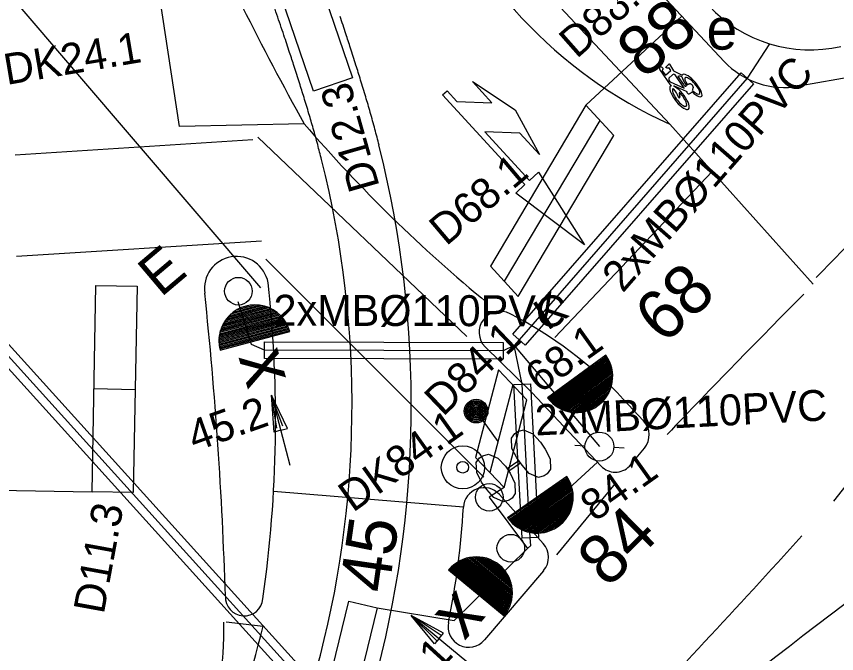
# Model space of a CAD drawing. Extents: x 81617 to 82144, y 454649 to 455150.
# Drawn here: x 81851.04 to 81870.9, y 454865.61 to 454881.04 of the extents above; entities that cross this region are included whole.
import ezdxf

# ---------------------------------------------------------------- set-up
doc = ezdxf.new("R2010")
doc.units = 0
for name, color, linetype in [('B-WE-OG-TOPOGRAFIE-G', 7, 'Continuous'), ('B-WE-VW-MARKERING-G', 7, 'Continuous'), ('N-OI-KL-VRI_KABEL_DETECTIE-G', 7, 'Continuous'), ('N-OI-KL-VRI_KABELGEUL-G', 7, 'Continuous'), ('N-OI-KL-VRI_LUS_DETECTIE-G', 7, 'Continuous'), ('N-OI-KL-VRI_LUS_DETECTIE-T18', 7, 'Continuous'), ('N-OI-KL-VRI_MANTELBUIS-G', 7, 'Continuous'), ('N-OI-KL-VRI_MANTELBUIS-T18', 7, 'Continuous'), ('N-WE-VW-VRI_ARMATUUR-S', 7, 'Continuous'), ('N-WE-VW-VRI_ARMATUUR-T18', 7, 'Continuous'), ('N-WE-VW-VRI_MAST-S', 7, 'Continuous'), ('N-WE-VW-VRI_RICHTINGNUMMER-T25', 7, 'Continuous')]:
    doc.layers.add(name, color=color, linetype=linetype)

msp = doc.modelspace()

# ---------------------------------------------------------------- linework, layer by layer
at = {"layer": 'B-WE-OG-TOPOGRAFIE-G'}
for p, q in [((81874.916, 454880.226), (81869.99, 454879.351)), ((81865.887, 454870.153), (81866.25, 454870.587))]:
    msp.add_line(p, q, dxfattribs=at)
for points in [[(81860.972, 454887.667), (81868.18, 454879.955)], [(81865.202, 454870.155), (81863.528, 454871.935), (81862.392, 454873.039)], [(81866.231, 454871.25), (81865.736, 454871.776)], [(81862.738, 454869.464), (81863.801, 454868.278)], [(81863.809, 454867.62), (81862.375, 454865.942)]]:
    msp.add_lwpolyline(points, dxfattribs=at)
for centre, radius, start, end in [((81384.425, 454720.912), 499.315, 18.68062, 18.74174), ((81759.42, 454847.652), 104.917, 18.31393, 18.55839), ((81739.67, 454841.022), 124.315, 18.55839, 18.68062), ((81759.42, 454847.652), 103.482, 18.31393, 18.55839), ((81795.02, 454859.436), 67.417, 18.00835, 18.31393), ((81795.02, 454859.436), 65.982, 18.00835, 18.31393), ((81804.078, 454862.38), 57.893, 17.58054, 18.00835), ((81869.641, 454881.321), 2, 223.0627, 280.0658), ((81804.078, 454862.38), 56.458, 17.5805, 18.0084), ((81816.845, 454866.425), 44.5, 17.0916, 17.5805), ((81816.845, 454866.425), 43.065, 17.0916, 17.5805), ((81821.112, 454867.737), 40.036, 16.4805, 17.0916), ((81821.112, 454867.737), 38.601, 16.4805, 17.0916), ((81827.65, 454869.672), 33.218, 15.8082, 16.4805), ((81827.65, 454869.672), 31.783, 15.8082, 16.4805), ((81830.107, 454870.367), 30.665, 15.0137, 15.8082), ((81830.107, 454870.367), 29.23, 15.0137, 15.8082), ((81834.087, 454871.435), 26.544, 14.1581, 15.0137), ((81834.856, 454871.629), 25.75, 315.1816, 14.1581), ((81834.087, 454871.435), 25.109, 14.1581, 15.0137), ((81834.856, 454871.629), 24.315, 315.1816, 14.1581), ((81856.374, 454874.452), 0.778, 10.5418, 188.3506), ((81826.72, 454871.27), 30.6, 351.8658, 6.2376), ((81757.01, 454863.938), 99.142, 1.77049, 6.02243), ((81862.757, 454873.393), 0.509, 61.9136, 224.1208), ((81858.393, 454864.888), 10.069, 43.1684, 62.7893), ((81865.867, 454870.908), 0.5, 320.0619, 43.2284), ((81865.545, 454870.475), 0.47, 222.9388, 316.7315), ((81862.366, 454869.13), 0.5, 41.8831, 176.883), ((81842.97, 454870.186), 18.925, 348.3581, 356.883), ((81863.429, 454867.945), 0.5, 319.4909, 41.8831), ((81856.559, 454866.98), 0.455, 177.4091, 354.9634), ((81861.995, 454866.266), 0.5, 168.3581, 319.4909)]:
    msp.add_arc(centre, radius, start, end, dxfattribs=at)
at = {"layer": 'B-WE-VW-MARKERING-G'}
for p, q in [((81854.993, 454878.378), (81853.979, 454885.079)), ((81856.964, 454874.469), (81850.333, 454882.22)), ((81862.559, 454878.95), (81862.086, 454879.466)), ((81862.086, 454879.466), (81863.118, 454878.784)), ((81861.364, 454879.143), (81861.475, 454879.244)), ((81863.359, 454876.969), (81861.364, 454879.143)), ((81861.475, 454879.244), (81861.712, 454878.986)), ((81861.712, 454878.986), (81862.559, 454878.95)), ((81863.118, 454878.784), (81863.709, 454877.697)), ((81866.865, 454878.432), (81870.34, 454874.562)), ((81863.235, 454878.213), (81862.388, 454878.25)), ((81862.388, 454878.25), (81863.469, 454877.071)), ((81863.709, 454877.697), (81863.235, 454878.213)), ((81851.016, 454877.689), (81856.772, 454878.062)), ((81856.894, 454878.118), (81861.952, 454873.29)), ((81863.469, 454877.071), (81863.69, 454877.273)), ((81863.69, 454877.273), (81864.8, 454875.509)), ((81867.894, 454877.286), (81864.079, 454873.271)), ((81863.138, 454876.766), (81863.359, 454876.969)), ((81864.8, 454875.509), (81863.138, 454876.766)), ((81851.048, 454875.238), (81856.977, 454875.611)), ((81857.08, 454875.163), (81862.361, 454869.888)), ((81857.003, 454874.502), (81857.002, 454874.502)), ((81865.114, 454870.249), (81863.429, 454868.694)), ((81865.539, 454869.733), (81864.122, 454868.002)), ((81861.867, 454869.157), (81857.268, 454869.534)), ((81856.127, 454866.379), (81857.019, 454866.277))]:
    msp.add_line(p, q, dxfattribs=at)
for points in [[(81860.959, 454884.75), (81866.865, 454878.432)], [(81866.902, 454879.365), (81866.629, 454879.747)], [(81866.661, 454879.824), (81866.706, 454879.784)], [(81866.681, 454879.727), (81866.76, 454879.618), (81866.89, 454879.737), (81866.842, 454879.807)], [(81866.862, 454879.889), (81866.957, 454879.73)], [(81866.931, 454879.63), (81866.844, 454879.551)], [(81866.878, 454879.457), (81867.215, 454879.31), (81866.998, 454879.63)], [(81866.957, 454879.73), (81867.167, 454879.625)], [(81867.061, 454879.585), (81867.194, 454879.392)], [(81866.975, 454879.361), (81867.263, 454879.234)], [(81867.417, 454879.247), (81867.417, 454879.247)], [(81858.01, 454878.446), (81854.993, 454878.378)]]:
    msp.add_lwpolyline(points, dxfattribs=at)
for centre, radius, start, end in [((81871.56, 454888.74), 11.327, 200.6243, 245.5093), ((81921.727, 454913.877), 72.905, 206.56935, 209.07707), ((82219.514, 454535.314), 486.895, 134.97926, 135.80708), ((81885.224, 454901.84), 35.888, 220.6875, 230.6195), ((81983.253, 454780.99), 142.962, 137.48788, 141.84973), ((82014.316, 454730.536), 203.636, 135.08452, 136.41908), ((81999.362, 454697.85), 212.13, 125.19968, 128.77534), ((81664.878, 455054.559), 277.009, 316.35043, 317.79319), ((81845.809, 454866.259), 10.261, 343.8323, 0.6213), ((81823.555, 454874.579), 34.479, 339.7444, 346.0669)]:
    msp.add_arc(centre, radius, start, end, dxfattribs=at)
for centre, major_axis, ratio, start_param, end_param in [((81866.74, 454879.732), (-0.0412, 0.0452), 0.951466, 6.106821, 7.217969), ((81866.911, 454879.52), (-0.0503, 0.0552), 0.951466, 0.416101, 1.916869), ((81866.966, 454879.588), (-0.0374, 0.0411), 0.951466, 4.868752, 6.235806), ((81867.403, 454879.371), (0.229, -0.262), 0.311979, 3.55346, 4.48315), ((81867.403, 454879.371), (0.229, -0.262), 0.311979, 5.055467, 9.526588), ((81867.411, 454879.363), (0.175, -0.195), 0.298624, 5.035956, 10.606751), ((81867.1, 454879.078), (0.217, -0.277), 0.337195, 2.965544, 8.864445), ((81867.403, 454879.371), (0.229, -0.262), 0.311979, 4.48315, 4.485286), ((81867.411, 454879.363), (0.175, -0.195), 0.298624, 4.323566, 4.330384), ((81867.101, 454879.079), (-0.163, 0.211), 0.305781, 6.11811, 11.365094), ((81866.943, 454879.273), (-0.0162, 0.0177), 0.951466, 4.515962, 5.19261), ((81866.627, 454878.971), (-0.325, 0.357), 0.951466, 4.25523, 4.724374), ((81867.349, 454879.175), (-0.177, 0.194), 0.951466, 0.769914, 1.166655), ((81867.099, 454879.198), (-0.00368, 0.00403), 0.951466, 5.132399, 7.244068), ((81867.093, 454879.093), (-0.0124, 0.0136), 0.951466, 0.933004, 4.202582)]:
    msp.add_ellipse(centre, major_axis=major_axis, ratio=ratio, start_param=start_param, end_param=end_param, dxfattribs=at)
for points in [[(81866.629, 454879.747), (81866.621, 454879.772), (81866.622, 454879.789), (81866.632, 454879.813), (81866.654, 454879.827), (81866.661, 454879.824)], [(81866.773, 454879.81), (81866.771, 454879.813), (81866.772, 454879.816), (81866.773, 454879.818), (81866.775, 454879.821), (81866.786, 454879.831), (81866.807, 454879.853), (81866.822, 454879.869), (81866.835, 454879.88), (81866.841, 454879.885), (81866.846, 454879.892), (81866.851, 454879.896), (81866.853, 454879.896), (81866.855, 454879.897), (81866.856, 454879.896), (81866.858, 454879.894), (81866.86, 454879.891), (81866.862, 454879.889), (81866.863, 454879.886)], [(81866.842, 454879.807), (81866.832, 454879.798), (81866.816, 454879.792), (81866.799, 454879.794), (81866.784, 454879.801), (81866.773, 454879.81)], [(81867.161, 454879.582), (81867.113, 454879.593), (81867.087, 454879.593), (81867.061, 454879.585)], [(81866.965, 454879.353), (81866.962, 454879.359), (81866.964, 454879.363), (81866.975, 454879.361)], [(81867.194, 454879.392), (81867.211, 454879.373), (81867.225, 454879.363), (81867.241, 454879.357), (81867.272, 454879.361)], [(81867.291, 454879.387), (81867.304, 454879.397), (81867.316, 454879.405), (81867.335, 454879.413), (81867.345, 454879.416), (81867.353, 454879.416), (81867.364, 454879.414), (81867.38, 454879.405), (81867.409, 454879.375), (81867.417, 454879.361), (81867.427, 454879.34), (81867.429, 454879.324), (81867.426, 454879.31), (81867.417, 454879.284), (81867.41, 454879.252)], [(81867.263, 454879.234), (81867.268, 454879.23), (81867.273, 454879.224), (81867.278, 454879.216), (81867.279, 454879.208), (81867.284, 454879.196), (81867.291, 454879.186), (81867.3, 454879.178), (81867.311, 454879.17), (81867.325, 454879.167), (81867.335, 454879.168), (81867.361, 454879.182), (81867.375, 454879.192), (81867.404, 454879.214)]]:
    msp.add_spline(points, degree=3, dxfattribs=at)
at = {"layer": 'N-OI-KL-VRI_KABEL_DETECTIE-G'}
for p, q in [((81864.836, 454878.895), (81867.16, 454881.046)), ((81847.104, 454869.626), (81852.875, 454869.531)), ((81862.852, 454869.634), (81862.493, 454869.399)), ((81859.776, 454866.72), (81861.647, 454866.417))]:
    msp.add_line(p, q, dxfattribs=at)
at = {"layer": 'N-OI-KL-VRI_KABELGEUL-G'}
for p, q in [((81863.097, 454873.073), (81865.161, 454870.624)), ((81862.493, 454869.399), (81863.421, 454868.157))]:
    msp.add_line(p, q, dxfattribs=at)
for points in [[(81869.281, 454880.381), (81868.742, 454879.546), (81863.215, 454873.214), (81863.097, 454873.073), (81862.831, 454872.946), (81857.049, 454872.96), (81856.734, 454873.094), (81856.416, 454874.128)], [(81862.44, 454851.616), (81862.582, 454852.027), (81862.754, 454852.346), (81865.008, 454854.754), (81865.955, 454855.815), (81865.903, 454856.153), (81846.599, 454877.513), (81846.252, 454877.634), (81845.96, 454877.281), (81846.114, 454876.473)], [(81861.647, 454866.417), (81863.421, 454868.157), (81863.498, 454868.233), (81863.487, 454868.417), (81863.292, 454872.136), (81863.097, 454873.073)]]:
    msp.add_lwpolyline(points, dxfattribs=at)
msp.add_arc((81870.263, 454883.584), 3.35, 223.0627, 282.8439, dxfattribs=at)
at = {"layer": 'N-OI-KL-VRI_LUS_DETECTIE-G'}
for p, q in [((81864.836, 454878.895), (81862.52, 454874.998)), ((81865.511, 454878.156), (81864.836, 454878.895)), ((81865.173, 454878.525), (81862.857, 454874.629)), ((81863.195, 454874.26), (81865.511, 454878.156)), ((81862.52, 454874.998), (81863.195, 454874.26)), ((81862.716, 454872.481), (81862.161, 454870.359)), ((81863.406, 454871.754), (81862.716, 454872.481)), ((81852.923, 454872.03), (81853.922, 454872.011)), ((81863.061, 454872.117), (81862.506, 454869.997)), ((81862.852, 454869.634), (81863.406, 454871.754)), ((81862.161, 454870.359), (81862.852, 454869.634))]:
    msp.add_line(p, q, dxfattribs=at)
for points in [[(81859.18, 454879.556), (81858.234, 454879.234), (81855.008, 454888.699), (81855.953, 454889.021)], [(81853.874, 454869.511), (81852.875, 454869.531), (81852.971, 454874.529), (81853.971, 454874.511)], [(81859.066, 454863.805), (81858.387, 454863.97), (81859.095, 454866.885), (81859.776, 454866.72)]]:
    msp.add_lwpolyline(points, close=True, dxfattribs=at)
at = {"layer": 'N-OI-KL-VRI_MANTELBUIS-G'}
for points in [[(81868.591, 454879.677), (81868.892, 454879.414), (81863.365, 454873.082), (81863.064, 454873.346)], [(81866.052, 454856.287), (81865.755, 454856.019), (81846.451, 454877.379), (81846.747, 454877.647)], [(81862.831, 454873.146), (81862.83, 454872.746), (81857.048, 454872.76), (81857.049, 454873.16)], [(81863.092, 454872.126), (81863.491, 454872.147), (81863.686, 454868.427), (81863.287, 454868.406)]]:
    msp.add_lwpolyline(points, close=True, dxfattribs=at)
at = {"layer": 'N-WE-VW-VRI_ARMATUUR-S'}
for p, q in [((81856.125, 454873.715), (81857.158, 454873.991)), ((81856.159, 454873.754), (81857.112, 454874.008)), ((81856.195, 454873.796), (81857.058, 454874.026)), ((81856.24, 454873.838), (81856.998, 454874.041)), ((81856.298, 454873.884), (81856.924, 454874.052)), ((81856.375, 454873.936), (81856.832, 454874.059)), ((81856.534, 454874.01), (81856.659, 454874.044)), ((81855.972, 454873.394), (81857.451, 454873.788)), ((81855.982, 454873.427), (81857.428, 454873.813)), ((81855.991, 454873.461), (81857.403, 454873.838)), ((81856.005, 454873.496), (81857.375, 454873.861)), ((81856.017, 454873.531), (81857.344, 454873.884)), ((81856.033, 454873.565), (81857.313, 454873.907)), ((81856.053, 454873.602), (81857.279, 454873.929)), ((81856.075, 454873.639), (81857.242, 454873.951)), ((81856.099, 454873.676), (81857.201, 454873.97)), ((81855.947, 454873.202), (81857.57, 454873.635)), ((81855.948, 454873.232), (81857.553, 454873.661)), ((81855.948, 454873.17), (81857.584, 454873.607)), ((81855.948, 454873.139), (81857.599, 454873.58)), ((81855.949, 454873.264), (81857.536, 454873.69)), ((81855.953, 454873.296), (81857.517, 454873.713)), ((81855.96, 454873.328), (81857.496, 454873.736)), ((81855.966, 454873.359), (81857.476, 454873.764)), ((81855.95, 454873.109), (81857.614, 454873.552)), ((81855.955, 454873.079), (81857.624, 454873.525)), ((81855.959, 454873.049), (81857.635, 454873.497)), ((81855.963, 454873.019), (81857.647, 454873.469)), ((81855.971, 454872.99), (81857.655, 454873.439)), ((81855.976, 454872.96), (81857.666, 454873.411)), ((81865.316, 454872.837), (81863.904, 454871.806)), ((81865.332, 454872.811), (81863.923, 454871.783)), ((81865.35, 454872.787), (81863.943, 454871.758)), ((81865.364, 454872.761), (81863.963, 454871.735)), ((81865.379, 454872.735), (81863.983, 454871.713)), ((81865.394, 454872.706), (81864.004, 454871.693)), ((81865.406, 454872.68), (81864.027, 454871.671)), ((81865.419, 454872.652), (81864.051, 454871.651)), ((81865.43, 454872.621), (81864.074, 454871.633)), ((81865.439, 454872.593), (81864.1, 454871.613)), ((81865.451, 454872.562), (81864.126, 454871.594)), ((81865.458, 454872.532), (81864.152, 454871.579)), ((81865.465, 454872.5), (81864.179, 454871.562)), ((81865.47, 454872.468), (81864.209, 454871.546)), ((81865.476, 454872.434), (81864.24, 454871.532)), ((81865.48, 454872.4), (81864.27, 454871.516)), ((81865.483, 454872.364), (81864.303, 454871.503)), ((81865.483, 454872.328), (81864.338, 454871.492)), ((81865.482, 454872.29), (81864.374, 454871.481)), ((81865.481, 454872.251), (81864.412, 454871.471)), ((81865.477, 454872.211), (81864.452, 454871.463)), ((81865.469, 454872.169), (81864.494, 454871.454)), ((81865.461, 454872.126), (81864.538, 454871.452)), ((81865.45, 454872.078), (81864.587, 454871.448)), ((81865.433, 454872.031), (81864.635, 454871.449)), ((81857.217, 454871.869), (81857.668, 454870.179)), ((81857.605, 454871.066), (81857.217, 454871.869)), ((81857.282, 454870.978), (81857.217, 454871.869)), ((81865.414, 454871.977), (81864.693, 454871.451)), ((81865.386, 454871.923), (81864.755, 454871.459)), ((81865.351, 454871.86), (81864.828, 454871.475)), ((81857.349, 454871.072), (81857.242, 454871.708)), ((81857.493, 454871.117), (81857.271, 454871.716)), ((81865.296, 454871.782), (81864.916, 454871.502)), ((81865.175, 454871.657), (81865.072, 454871.579)), ((81862.344, 454871.243), (81862.698, 454870.746)), ((81857.443, 454871.023), (81857.282, 454870.978)), ((81857.443, 454871.023), (81857.605, 454871.066)), ((81863.187, 454870.993), (81863.323, 454871.028)), ((81863.323, 454871.028), (81863.549, 454870.933)), ((81863.031, 454870.827), (81863.113, 454870.942)), ((81863.044, 454870.581), (81863.031, 454870.827)), ((81863.113, 454870.942), (81863.187, 454870.993)), ((81863.549, 454870.933), (81863.736, 454870.736)), ((81863.736, 454870.736), (81863.851, 454870.566)), ((81862.26, 454870.351), (81862.338, 454870.403)), ((81862.338, 454870.403), (81862.473, 454870.438)), ((81862.473, 454870.438), (81862.698, 454870.346)), ((81863.165, 454870.354), (81863.044, 454870.581)), ((81863.851, 454870.566), (81863.967, 454870.325)), ((81862.18, 454870.239), (81862.26, 454870.351)), ((81862.192, 454869.996), (81862.18, 454870.239)), ((81862.698, 454870.346), (81862.884, 454870.151)), ((81863.213, 454870.279), (81862.929, 454870.083)), ((81863.247, 454870.225), (81862.964, 454870.027)), ((81863.287, 454870.174), (81863.165, 454870.354)), ((81863.967, 454870.325), (81863.977, 454870.081)), ((81862.884, 454870.151), (81862.999, 454869.981)), ((81863.461, 454869.975), (81863.287, 454870.174)), ((81863.977, 454870.081), (81863.898, 454869.964)), ((81862.309, 454869.767), (81862.192, 454869.996)), ((81864.371, 454869.897), (81862.935, 454868.903)), ((81864.388, 454869.872), (81862.952, 454868.88)), ((81864.405, 454869.847), (81862.972, 454868.855)), ((81864.418, 454869.82), (81862.991, 454868.832)), ((81862.999, 454869.981), (81863.114, 454869.736)), ((81863.687, 454869.878), (81863.461, 454869.975)), ((81863.822, 454869.915), (81863.687, 454869.878)), ((81863.898, 454869.964), (81863.822, 454869.915)), ((81862.433, 454869.587), (81862.309, 454869.767)), ((81864.434, 454869.794), (81863.011, 454868.809)), ((81864.447, 454869.765), (81863.033, 454868.788)), ((81864.459, 454869.736), (81863.053, 454868.765)), ((81864.472, 454869.709), (81863.077, 454868.746)), ((81864.481, 454869.679), (81863.101, 454868.726)), ((81863.114, 454869.736), (81863.124, 454869.489)), ((81864.49, 454869.651), (81863.124, 454868.705)), ((81864.501, 454869.618), (81863.151, 454868.686)), ((81862.606, 454869.389), (81862.433, 454869.587)), ((81863.124, 454869.489), (81863.048, 454869.374)), ((81864.506, 454869.589), (81863.177, 454868.671)), ((81864.513, 454869.558), (81863.202, 454868.653)), ((81864.516, 454869.523), (81863.234, 454868.635)), ((81864.523, 454869.491), (81863.264, 454868.622)), ((81864.526, 454869.457), (81863.292, 454868.604)), ((81864.527, 454869.419), (81863.326, 454868.592)), ((81862.836, 454869.29), (81862.606, 454869.389)), ((81862.972, 454869.326), (81862.836, 454869.29)), ((81863.048, 454869.374), (81862.972, 454869.326)), ((81864.528, 454869.383), (81863.36, 454868.579)), ((81864.526, 454869.345), (81863.395, 454868.566)), ((81864.524, 454869.307), (81863.434, 454868.557)), ((81864.518, 454869.267), (81863.474, 454868.546)), ((81864.507, 454869.225), (81863.514, 454868.536)), ((81864.501, 454869.182), (81863.56, 454868.532)), ((81864.486, 454869.135), (81863.609, 454868.529)), ((81864.47, 454869.09), (81863.655, 454868.527)), ((81864.447, 454869.036), (81863.715, 454868.528)), ((81864.421, 454868.981), (81863.777, 454868.536)), ((81864.383, 454868.918), (81863.848, 454868.549)), ((81864.327, 454868.843), (81863.937, 454868.573)), ((81864.199, 454868.721), (81864.094, 454868.646)), ((81861.739, 454867.837), (81863.008, 454866.794)), ((81861.769, 454867.852), (81863.015, 454866.823)), ((81861.798, 454867.865), (81863.025, 454866.854)), ((81861.827, 454867.88), (81863.034, 454866.887)), ((81861.86, 454867.893), (81863.039, 454866.921)), ((81861.89, 454867.906), (81863.046, 454866.954)), ((81861.925, 454867.916), (81863.052, 454866.989)), ((81861.961, 454867.926), (81863.054, 454867.026)), ((81861.996, 454867.936), (81863.055, 454867.063)), ((81862.035, 454867.943), (81863.055, 454867.101)), ((81862.073, 454867.949), (81863.053, 454867.143)), ((81862.118, 454867.952), (81863.053, 454867.185)), ((81862.161, 454867.956), (81863.044, 454867.229)), ((81862.211, 454867.956), (81863.033, 454867.277)), ((81862.259, 454867.952), (81863.021, 454867.324)), ((81862.316, 454867.947), (81863.005, 454867.377)), ((81862.377, 454867.934), (81862.981, 454867.438)), ((81862.446, 454867.916), (81862.948, 454867.505)), ((81862.535, 454867.881), (81862.901, 454867.582)), ((81861.507, 454867.638), (81862.857, 454866.528)), ((81861.529, 454867.659), (81862.876, 454866.551)), ((81861.547, 454867.683), (81862.895, 454866.577)), ((81861.571, 454867.703), (81862.91, 454866.601)), ((81861.592, 454867.724), (81862.927, 454866.625)), ((81861.615, 454867.747), (81862.943, 454866.651)), ((81861.638, 454867.765), (81862.957, 454866.681)), ((81861.661, 454867.785), (81862.97, 454866.706)), ((81861.687, 454867.802), (81862.983, 454866.735)), ((81861.714, 454867.819), (81862.995, 454866.764)), ((81862.686, 454867.795), (81862.789, 454867.714)), ((81860.603, 454866.537), (81861.949, 454865.424)), ((81861.169, 454865.85), (81860.603, 454866.537)), ((81861.382, 454866.109), (81860.603, 454866.537)), ((81861.333, 454866.048), (81860.603, 454866.537)), ((81861.226, 454865.917), (81860.603, 454866.537)), ((81861.277, 454865.978), (81861.382, 454866.109)), ((81861.277, 454865.978), (81861.169, 454865.85))]:
    msp.add_line(p, q, dxfattribs=at)
for centre, radius in [((81862.175, 454871.484), 0.286), ((81862.175, 454871.484), 0.256), ((81862.175, 454871.484), 0.226), ((81862.175, 454871.484), 0.196), ((81862.175, 454871.484), 0.166), ((81862.175, 454871.484), 0.136), ((81862.175, 454871.484), 0.106), ((81862.175, 454871.484), 0.0765), ((81862.175, 454871.484), 0.0465), ((81862.175, 454871.484), 0.0165), ((81861.855, 454870.121), 0.522), ((81861.85, 454870.124), 0.141)]:
    msp.add_circle(centre, radius, dxfattribs=at)
for centre, start, end in [((81856.821, 454873.185), 14.936, 194.936), ((81864.61, 454872.322), 216.1278, 36.1278), ((81863.654, 454869.401), 214.6317, 34.6317), ((81862.183, 454867.082), 320.5187, 140.5187)]:
    msp.add_arc(centre, 0.873, start, end, dxfattribs=at)
at = {"layer": 'N-WE-VW-VRI_MAST-S'}
for p, q in [((81864.562, 454870.658), (81864.812, 454870.644)), ((81865.76, 454870.591), (81865.511, 454870.605))]:
    msp.add_line(p, q, dxfattribs=at)
for centre, radius in [((81856.42, 454874.389), 0.335), ((81865.161, 454870.624), 0.35), ((81862.493, 454869.399), 0.335), ((81863.016, 454868.164), 0.335)]:
    msp.add_circle(centre, radius, dxfattribs=at)

# ---------------------------------------------------------------- texts
at = {"layer": 'B-WE-OG-TOPOGRAFIE-G'}
msp.add_text('e', height=1, dxfattribs=at).set_placement((81867.755, 454880.24))
msp.add_text('E', height=1, rotation=40.2193, dxfattribs=at).set_placement((81854.541, 454874.224))
at = {"layer": 'N-OI-KL-VRI_LUS_DETECTIE-T18'}
for s, rotation, p in [('D88.1', 41.4026, (81864.608, 454880.003)), ('D12.3', 105.8368, (81859.844, 454876.926)), ('D68.1', 40.2842, (81861.449, 454875.466)), ('D84.1', 43.7059, (81861.372, 454871.333)), ('D11.3', 79.6417, (81853.159, 454866.548))]:
    msp.add_text(s, height=0.75, rotation=rotation, dxfattribs=at).set_placement(p)
at = {"layer": 'N-OI-KL-VRI_MANTELBUIS-T18'}
for rotation, p in [(48.88, (81865.727, 454874.328)), (359.86, (81857.267, 454873.553)), (3, (81863.621, 454870.892))]:
    msp.add_text('2xMB%%C110PVC', height=0.75, rotation=rotation, dxfattribs=at).set_placement(p)
at = {"layer": 'N-WE-VW-VRI_ARMATUUR-S'}
for s, height, rotation, p in [('K', 0.75, 33.7771, (81863.903, 454873.422)), ('x', 1.26, 286.436, (81856.417, 454872.798)), ('x', 1.26, 229.0187, (81861.704, 454867.169))]:
    msp.add_text(s, height=height, rotation=rotation, dxfattribs=at).set_placement(p)
at = {"layer": 'N-WE-VW-VRI_ARMATUUR-T18'}
for s, rotation, p in [('DK24.1', 9.603, (81850.809, 454879.383)), ('68.1', 35.4794, (81863.719, 454871.896)), ('45.2', 19.5328, (81855.36, 454870.498)), ('DK84.1', 35.4794, (81859.192, 454869.016)), ('84.1', 35.4794, (81865.048, 454868.79)), ('45.1', 47.6296, (81860.337, 454864.127))]:
    msp.add_text(s, height=0.75, rotation=rotation, dxfattribs=at).set_placement(p)
at = {"layer": 'N-WE-VW-VRI_RICHTINGNUMMER-T25'}
for s, rotation, p in [('88', 40, (81866.238, 454879.502)), ('68', 43.0356, (81866.727, 454873.078)), ('84', 44.5598, (81865.364, 454867.177)), ('45', 81.7907, (81860.053, 454867.054))]:
    msp.add_text(s, height=1.2, rotation=rotation, dxfattribs=at).set_placement(p)

doc.saveas('drawing.dxf')
